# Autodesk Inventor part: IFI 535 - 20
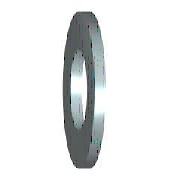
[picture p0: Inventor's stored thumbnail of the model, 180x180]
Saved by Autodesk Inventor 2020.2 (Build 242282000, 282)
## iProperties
Manager: www.cadconsulting.pl
Company: Fabian Stasiak CAD Consulting
Created: 2006-02
Part Number: IFI 535 - 20
Material: Stal, miękka
Description: Podkładka okrągła skośna - Metryczny
Document SubType Name: Modeling
Standard: IFI 535
Designer: F.Stasiak
Standards Organization: ANSI
Language: pl-PL
Size Designation: 20
Categories: <MemberInstance><Categories><Category DisplayName="Mocowania" InternalName="e4da775c-781d-43d5-af7c-5136215cf5a6" Mnemonic="FSTN"><Category DisplayName="Podkład
Density: 1 g/cm^3
Appearance: Stal
Author: F.Stasiak
Subject: Zbiór ćwiczeń. Autodesk Inventor 2020. Kurs podstawowy
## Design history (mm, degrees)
sketch "Szkic"
  geometry: C1 r 21 at (0, 0); C2 r 11 at (0, 0); 1 further point
  constraints: 2 centre point, 2 coincident
  dimensions: "d0" = 22 diameter of C2 (= SD1); "d1" = 42 diameter of C1 (= SD2)
extrude "Bryła" new body sketch "Szkic" distance "d2" = 4.6 (= SD); taper "d3" = 0 deg
workaxis "Work Axis1"
workplane "Work Plane1"
node "Bryła1"
node "Korpusy bryłowe"
node "Korpusy powierzchniowe"
other parameters: "SD1" = 22 [user parameter; used in 1 equation term], "SD2" = 42 [user parameter; used in 1 equation term], "SD" = 4.6 [user parameter; used in 1 equation term], "d4" = 0, "d5" = 0, "d6" = 0, "d7" = 0
